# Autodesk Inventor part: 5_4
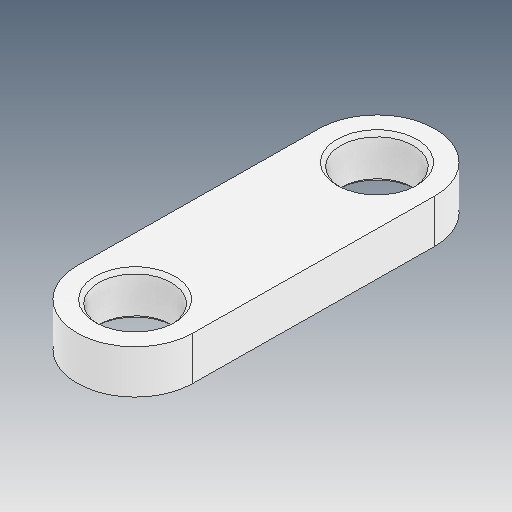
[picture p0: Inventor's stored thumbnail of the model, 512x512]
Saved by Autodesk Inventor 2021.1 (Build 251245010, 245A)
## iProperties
Created: 2021-06
Part Number: 5_4
Material: Ogólny
Document SubType Name: Modeling
Designer: user
Density: 1 g/cm^3
Appearance: Domyślna
Author: user
Revision Number: ÈÎºÎ
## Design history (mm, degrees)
feature "ÊäÈë1"
node "Bryła1"
